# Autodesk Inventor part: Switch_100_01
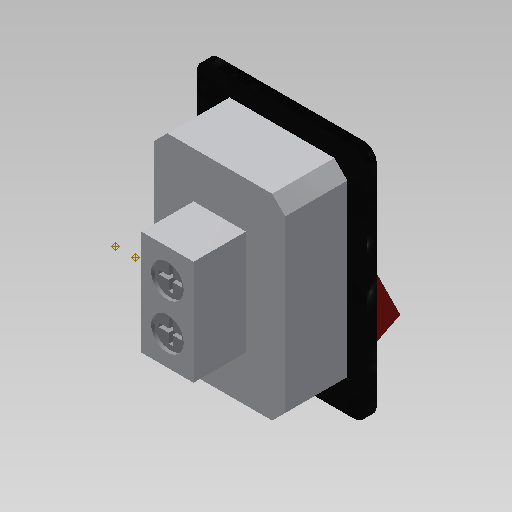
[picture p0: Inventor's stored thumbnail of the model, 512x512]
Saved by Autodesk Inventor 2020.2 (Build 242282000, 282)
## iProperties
Created: 2014-09
Part Number: Switch_100_01
Material: Ogólny
Document SubType Name: Modeling
Designer: F.Stasiak
Density: 1 g/cm^3
Appearance: Domyślna
Catalog Web Link: www.expertbooks.pl
Manager: www.cadconsulting.pl
Company: Fabian Stasiak CAD Consulting
GlobalPropertyList: <PropertyList/>
Author: F.Stasiak
Subject: Zbiór ćwiczeń. Autodesk Inventor 2020. Kurs Professional
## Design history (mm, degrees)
sketch "Szkic1"
  geometry: L1 (-10, 15)-(10, 15); L2 (10, 15)-(10, -15); L3 (10, -15)-(-10, -15); L4 (-10, -15)-(-10, 15); L5 (-10, 15)-(10, -15); L6 (10, 15)-(-10, -15); 1 further point
  constraints: 12 end point, 2 equal length, 2 midpoint, 1 horizontal, 1 parallel
  dimensions: "d0" = 20 distance of L2.end L3.end; "d1" = 30 distance of L1.end L2.end
extrude "Wyciągnięcie proste1" new body sketch "Szkic1" distance "d2" = 12; taper "d3" = 0 deg
node "Płaszczyzna konstrukcyjna1"
sketch "Szkic2"
  geometry: L1 (10, 15)-(-10, 15) reference; L2 (-10, 15)-(-10, -15) reference; L3 (-10, -15)-(10, -15) reference; L4 (10, -15)-(10, 15) reference; L5 (-13, 18)-(13, 18); L6 (13, 18)-(13, -18); L7 (13, -18)-(-13, -18); L8 (-13, -18)-(-13, 18); 1 further point
  constraints: 8 end point, 3 other
  dimensions: "d5" = 3 distance between parallel lines of L1 L5
extrude "Wyciągnięcie proste2" join sketch "Szkic2" distance "d6" = 1.5; taper "d7" = 0 deg
fillet "Zaokrąglenie1" dims "d8" = 2
chamfer "Faza1" distance "d9" = 2; stored, may be unused: second distance "d10" = 2, angle "d11" = 45 deg
sketch "Szkic3"
  geometry: L1 (15, 0)-(-15, 0) reference; L2 (-15, 0)-(15, 0) reference; L3 (13.059, 0)-(13.059, -1.168); L4 (13.059, -1.168)-(0.743, -1.599); L5 (0.743, -1.599)-(-10.298, -7.075); L6 (-10.298, -7.075)-(-13.229, -1.168); L7 (-13.229, -1.168)-(-13.229, 0); 1 further point
  constraints: 10 end point, 3 perpendicular, 2 equal length, 2 point on line
extrude "Wyciągnięcie proste3" join sketch "Szkic3" stored distance "d12" = 17; taper "d13" = 0 deg
sketch "Szkic4"
  geometry: L1 (4, 8)-(-4, 8); L2 (-4, 8)-(-4, -8); L3 (-4, -8)-(4, -8); L4 (4, -8)-(4, 8); L5 (4, 8)-(-4, -8); L6 (-4, 8)-(4, -8); 1 further point
  constraints: 12 end point, 2 midpoint, 2 parallel, 1 horizontal, 1 perpendicular
  dimensions: "d14" = 8 distance of L3.end L2.end; "d15" = 16 distance of L2.end L1.end
extrude "Wyciągnięcie proste4" join sketch "Szkic4" distance "d16" = 8; taper "d17" = 0 deg
sketch "Szkic5"
  geometry: L1 (0, 0)-(0, 16) reference; L2 (0, 0)-(8, 0) reference; L3 (8, 16)-(8, 0) reference; L4 (0, 16)-(8, 16) reference; L5 (4, 11.5)-(4, 4.5); C1 r 2 at (4, 11.5); C2 r 2 at (4, 4.5); 5 further points
  constraints: 4 midpoint, 2 centre point, 2 end point, 2 vertical alignment, 1 equal radius, 1 horizontal alignment, 1 vertical
  dimensions: "d18" = 4 diameter of C1; "d19" = 7 distance of L5.end L5.start
extrude "Wyciągnięcie proste5" cut sketch "Szkic5" distance "d20" = 5; taper "d21" = 0 deg
sketch "Szkic6"
  geometry: L1 (1, 1.5)-(1, 5.5) reference; L2 (-4, 1.5)-(-4, 5.5) reference; L3 (1, -5.5)-(1, -1.5) reference; L4 (-4, -5.5)-(-4, -1.5) reference; L5 (4, 8)-(-4, 8) reference; L6 (-4, 8)-(-4, -8) reference; L7 (-4, -8)-(4, -8) reference; L8 (4, -8)-(4, 8) reference; C1 r 2.5 at (0, 3.5); C2 r 2.5 at (0, -3.5); 2 further points
  constraints: 2 centre point, 2 midpoint, 2 vertical alignment, 1 equal radius
  dimensions: "d22" = 7 distance of C1.centre C2.centre; "d23" = 5 diameter of C2
extrude "Wyciągnięcie proste6" cut sketch "Szkic6" distance "d24" = 0.5; taper "d25" = 0 deg
sketch "Szkic7"
  geometry: L1 (0.3, 1.75)-(-0.3, 1.75); L2 (-0.3, 1.75)-(-0.3, -1.75); L3 (-0.3, -1.75)-(0.3, -1.75); L4 (0.3, -1.75)-(0.3, 1.75); L5 (0.3, 1.75)-(-0.3, -1.75); L6 (-0.3, 1.75)-(0.3, -1.75); L7 (1.8, 0.3)-(-1.8, 0.3); L8 (-1.8, 0.3)-(-1.8, -0.3); L9 (-1.8, -0.3)-(1.8, -0.3); L10 (1.8, -0.3)-(1.8, 0.3); L11 (1.8, 0.3)-(-1.8, -0.3); L12 (-1.8, 0.3)-(1.8, -0.3); 3 further points
  constraints: 24 end point, 5 midpoint, 4 parallel, 2 horizontal, 2 perpendicular
  dimensions: "d26" = 0.6 distance of L3.end L2.end; "d27" = 3.5 distance of L2.end L1.end; "d28" = 3.6 distance of L9.end L8.end; "d29" = 0.6 distance of L8.end L7.end
extrude "Wyciągnięcie proste7" cut sketch "Szkic7" distance "d30" = 1; taper "d31" = -5 deg
mirror "Odbicie lustrzane1"
chamfer "Faza2" distance "d32" = 1; stored, may be unused: second distance "d33" = 2, angle "d34" = 45 deg
sketch "Szkic8"
  geometry: C1 r 2 at (4, 11.5) reference
node "S1"
sketch "Szkic9"
  geometry: C1 r 2 at (4, 4.5) reference
node "S2"
chamfer "Faza3" distance "d35" = 1; stored, may be unused: second distance "d36" = 2, angle "d37" = 45 deg
node "Płaszczyzna konstrukcyjna2"
node "Płaszczyzna konstrukcyjna3"
node "Płaszczyzna konstrukcyjna4"
node "Punkt konstrukcyjny3"
node "Punkt konstrukcyjny4"
node "Bryła1"
node "Pętla rzutowana1"
node "Pętla rzutowana2"
node "Pętla rzutowana3"
node "Pętla rzutowana4"
node "Pętla rzutowana5"
other parameters: "d4" = -1, "d38" = 5, "d39" = 3
